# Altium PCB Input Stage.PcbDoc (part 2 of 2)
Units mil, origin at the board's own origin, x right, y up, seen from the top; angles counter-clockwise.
Board outline 5000 x 8750 mil, 6 copper layers (Top Layer, Layer 1, Layer 2, Layer 3, Layer 4, Bottom Layer), stack 91 mil thick; 55 components, 34 nets, 272 pads, 68 vias.
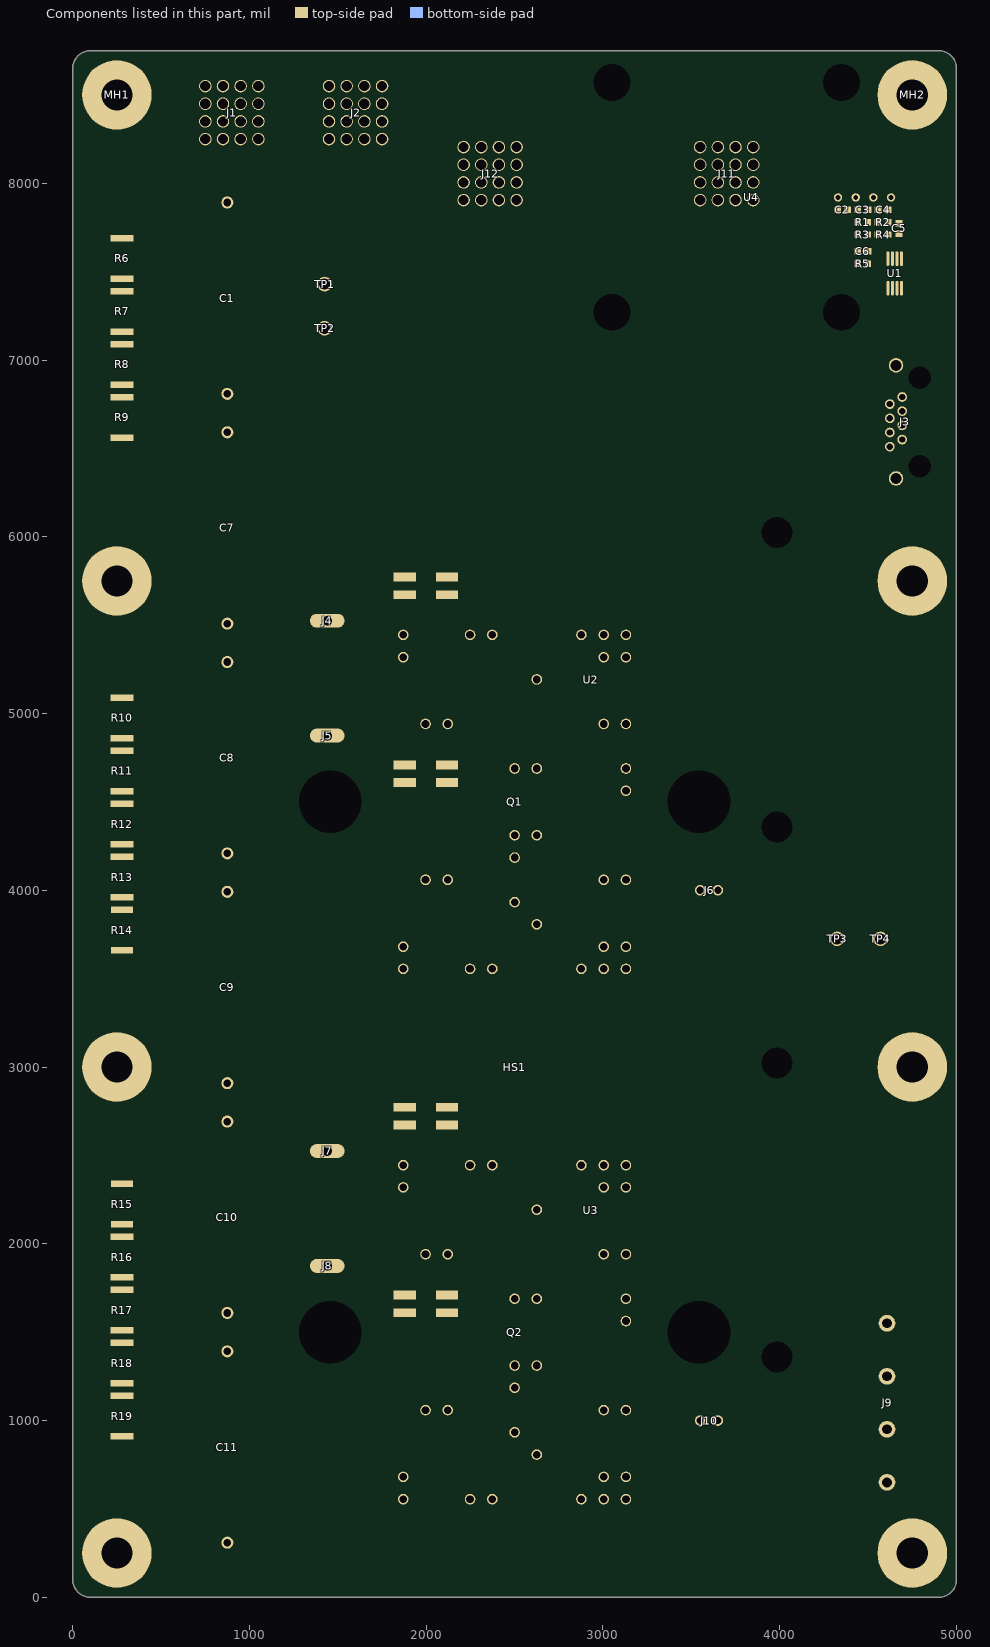
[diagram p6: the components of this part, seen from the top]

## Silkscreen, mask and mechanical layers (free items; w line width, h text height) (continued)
Drill Drawing:
  drawing of 152 lines, arcs and shapes, not listed
  text "*" at 140,11885 h60
  text "THESE HOLES (1.10MM +/- 0.05MM) ARE FOR PRESS-FIT PART. USE 47.2MIL +/- 1MIL DRILLED HOLES. COPPER THICKNESS IN HOLE 25-50UM." at 232.5,11827.5 h100
  text "w" at 6.76,11802.31 h200
  text "^" at 145,11700.01 h60
  text "THESE HOLES (1.48MM +/- 0.05MM) ARE FOR PRESS-FIT PART. USE 63.0MIL +/- 1MIL DRILLED HOLES. COPPER THICKNESS IN HOLE 25-60UM." at 237.5,11632.5 h100
  text "w" at 13.3,11614.25 h200
  text "Symbol" at 97.5,11452.5 h72
  text "Count" at 603.38,11452.5 h72
  text "Hole Size" at 1203.22,11452.5 h72
  text "Plated" at 2302.9,11452.5 h72
  text "Hole Type" at 2808.77,11452.5 h72
  text "Drill Layer Pair" at 3542.57,11452.5 h72
  text "Via/Pad" at 5042.13,11452.5 h72
  text "Pad Shape" at 5631.97,11452.5 h72
  text "Hole Tolerance (+)" at 6377.77,11452.5 h72
  text "Hole Tolerance (-)" at 7711.38,11452.5 h72
  text "68" at 603.38,11302.5 h60
  text "0.51mm (20.00mil)" at 1203.22,11302.5 h60
  text "PTH" at 2302.9,11302.5 h60
  text "Round" at 2808.77,11302.5 h60
  text "Top Layer - Bottom Layer" at 3542.57,11302.5 h60
  text "Via" at 5042.13,11302.5 h60
  text "Rounded" at 5631.97,11302.5 h60
  text "0.08mm (3.00mil)" at 6377.77,11302.5 h60
  text "0.08mm (3.00mil)" at 7711.38,11302.5 h60
  text "4" at 603.38,11152.5 h60
  text "0.70mm (27.56mil)" at 1203.22,11152.5 h60
  text "PTH" at 2302.9,11152.5 h60
  text "Round" at 2808.77,11152.5 h60
  text "Top Layer - Bottom Layer" at 3542.57,11152.5 h60
  text "Pad" at 5042.13,11152.5 h60
  text "Rounded" at 5631.97,11152.5 h60
  text "0.08mm (3.00mil)" at 6377.77,11152.5 h60
  text "0.08mm (3.00mil)" at 7711.38,11152.5 h60
  text "8" at 603.38,11002.5 h60
  text "0.89mm (35.04mil)" at 1203.22,11002.5 h60
  text "PTH" at 2302.9,11002.5 h60
  text "Round" at 2808.77,11002.5 h60
  text "Top Layer - Bottom Layer" at 3542.57,11002.5 h60
  text "Pad" at 5042.13,11002.5 h60
  text "Rounded" at 5631.97,11002.5 h60
  text "0.08mm (3.00mil)" at 6377.77,11002.5 h60
  text "0.08mm (3.00mil)" at 7711.38,11002.5 h60
  text "B" at 68.41,10992.51 h66.67
  text "4" at 603.38,10852.5 h60
  text "1.02mm (40.16mil)" at 1203.22,10852.5 h60
  text "PTH" at 2302.9,10852.5 h60
  text "Round" at 2808.77,10852.5 h60
  text "Top Layer - Bottom Layer" at 3542.57,10852.5 h60
  text "Pad" at 5042.13,10852.5 h60
  text "Rounded" at 5631.97,10852.5 h60
  text "0.08mm (3.00mil)" at 6377.77,10852.5 h60
  text "0.08mm (3.00mil)" at 7711.38,10852.5 h60
  text "12" at 603.38,10702.5 h60
  text "1.10mm (43.31mil)" at 1203.22,10702.5 h60
  text "PTH" at 2302.9,10702.5 h60
  text "Round" at 2808.77,10702.5 h60
  text "Top Layer - Bottom Layer" at 3542.57,10702.5 h60
  text "Pad" at 5042.13,10702.5 h60
  text "Rounded" at 5631.97,10702.5 h60
  text "0.08mm (3.00mil)" at 6377.77,10702.5 h60
  text "0.08mm (3.00mil)" at 7711.38,10702.5 h60
  text "*" at -85,10605 h60
  text "72" at 603.38,10552.5 h60
  text "1.10mm (43.31mil)" at 1203.22,10552.5 h60
  text "PTH" at 2302.9,10552.5 h60
  text "Round" at 2808.77,10552.5 h60
  text "Top Layer - Bottom Layer" at 3542.57,10552.5 h60
  text "Pad" at 5042.13,10552.5 h60
  text "Rounded" at 5631.97,10552.5 h60
  text "0.05mm (1.97mil)" at 6377.77,10552.5 h60
  text "0.05mm (1.97mil)" at 7711.38,10552.5 h60
  text "w" at -215.74,10524.81 h200
  text "8" at 603.38,10402.5 h60
  text "1.40mm (55.12mil)" at 1203.22,10402.5 h60
  text "PTH" at 2302.9,10402.5 h60
  text "Round" at 2808.77,10402.5 h60
  text "Top Layer - Bottom Layer" at 3542.57,10402.5 h60
  text "Pad" at 5042.13,10402.5 h60
  text "Rounded" at 5631.97,10402.5 h60
  text "0.08mm (3.00mil)" at 6377.77,10402.5 h60
  text "0.08mm (3.00mil)" at 7711.38,10402.5 h60
  text "^" at -94.38,10320.84 h60
  text "64" at 603.38,10252.5 h60
  text "1.48mm (58.07mil)" at 1203.22,10252.5 h60
  text "PTH" at 2302.9,10252.5 h60
  text "Round" at 2808.77,10252.5 h60
  text "Top Layer - Bottom Layer" at 3542.57,10252.5 h60
  text "Pad" at 5042.13,10252.5 h60
  text "Rounded" at 5631.97,10252.5 h60
  text "0.05mm (1.97mil)" at 6377.77,10252.5 h60
  text "0.05mm (1.97mil)" at 7711.38,10252.5 h60
  text "w" at -223.57,10237.58 h200
  text "2" at 603.38,10102.5 h60
  text "1.57mm (61.81mil)" at 1203.22,10102.5 h60
  text "PTH" at 2302.9,10102.5 h60
  text "Round" at 2808.77,10102.5 h60
  text "Top Layer - Bottom Layer" at 3542.57,10102.5 h60
  text "Pad" at 5042.13,10102.5 h60
  text "Rounded" at 5631.97,10102.5 h60
  text "0.08mm (3.00mil)" at 6377.77,10102.5 h60
  text "0.08mm (3.00mil)" at 7711.38,10102.5 h60
  text "C" at 68.41,10092.51 h66.67
  text "4" at 603.38,9952.5 h60
  text "1.60mm (62.99mil)" at 1203.22,9952.5 h60
  text "PTH" at 2302.9,9952.5 h60
  text "Round" at 2808.77,9952.5 h60
  text "Top Layer - Bottom Layer" at 3542.57,9952.5 h60
  text "Pad" at 5042.13,9952.5 h60
  text "Rounded" at 5631.97,9952.5 h60
  text "0.08mm (3.00mil)" at 6377.77,9952.5 h60
  text "0.08mm (3.00mil)" at 7711.38,9952.5 h60
  text "2" at 603.38,9802.5 h60
  text "3.25mm (127.95mil)" at 1203.22,9802.5 h60
  text "NPTH" at 2302.9,9802.5 h60
  text "Round" at 2808.77,9802.5 h60
  text "Top Layer - Bottom Layer" at 3542.57,9802.5 h60
  text "Pad" at 5042.13,9802.5 h60
  text "Rounded" at 5631.97,9802.5 h60
  text "0.13mm (5.00mil)" at 6377.77,9802.5 h60
  text "0.13mm (5.00mil)" at 7711.38,9802.5 h60
  text "D" at 68.41,9792.51 h66.67
  text "4" at 603.38,9652.5 h60
  text "4.45mm (175.00mil)" at 1203.22,9652.5 h60
  text "NPTH" at 2302.9,9652.5 h60
  text "Round" at 2808.77,9652.5 h60
  text "Top Layer - Bottom Layer" at 3542.57,9652.5 h60
  text "Pad" at 5042.13,9652.5 h60
  text "Rounded" at 5631.97,9652.5 h60
  text "0.13mm (5.00mil)" at 6377.77,9652.5 h60
  text "0.13mm (5.00mil)" at 7711.38,9652.5 h60
  text "8" at 603.38,9502.5 h60
  text "4.50mm (177.17mil)" at 1203.22,9502.5 h60
  text "PTH" at 2302.9,9502.5 h60
  text "Round" at 2808.77,9502.5 h60
  text "Top Layer - Bottom Layer" at 3542.57,9502.5 h60
  text "Pad" at 5042.13,9502.5 h60
  text "Rounded" at 5631.97,9502.5 h60
  text "0.13mm (5.00mil)" at 6377.77,9502.5 h60
  text "0.13mm (5.00mil)" at 7711.38,9502.5 h60
  text "4" at 603.38,9352.5 h60
  text "5.30mm (208.66mil)" at 1203.22,9352.5 h60
  text "NPTH" at 2302.9,9352.5 h60
  text "Round" at 2808.77,9352.5 h60
  text "Top Layer - Bottom Layer" at 3542.57,9352.5 h60
  text "Pad" at 5042.13,9352.5 h60
  text "Rounded" at 5631.97,9352.5 h60
  text "0.13mm (5.00mil)" at 6377.77,9352.5 h60
  text "0.13mm (5.00mil)" at 7711.38,9352.5 h60
  text "4" at 603.38,9202.5 h60
  text "9.00mm (354.33mil)" at 1203.22,9202.5 h60
  text "NPTH" at 2302.9,9202.5 h60
  text "Round" at 2808.77,9202.5 h60
  text "Top Layer - Bottom Layer" at 3542.57,9202.5 h60
  text "Pad" at 5042.13,9202.5 h60
  text "Rounded" at 5631.97,9202.5 h60
  text "0.13mm (5.00mil)" at 6377.77,9202.5 h60
  text "0.13mm (5.00mil)" at 7711.38,9202.5 h60
  text "268 Total" at 603.38,9052.5 h60

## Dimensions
100,0 to 100,8750 on Drill Drawing
0,100 to 5000,100 on Drill Drawing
